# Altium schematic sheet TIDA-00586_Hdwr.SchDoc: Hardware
size 431 x 279 mm; Date: Not shown in title block; ApprovedBy: Not shown in title block; CheckedBy: Not shown in title block; Author: Not shown in title block; CompanyName: Not shown in title block; DrawnBy: Jared Casey; Engineer: Not shown in title block; Organization: Not shown in title block; Address1: Not shown in title block; Address2: Not shown in title block; Address3: Not shown in title block; Address4: Not shown in title block; DocumentNumber: 1; Revision: Use project parameter SCH_Rev; SheetNumber: 7; SheetTotal: 7; PageSetup: Record=PageOptions¦CenterHorizontal=True¦CenterVertical=True¦PrintScale=1.00¦XCorrection=1.00¦YCorrection=1.00¦PrintKind=0¦BorderSize=5000000¦LeftOffset=0¦BottomOffset=0¦Orientation=2¦PaperLength=1000¦PaperWidth=1000¦Scale=100¦PaperSource=15¦PrintQuality=600¦MediaType=1¦DitherType=10¦PaperKind=Letter¦PrintScaleMode=1
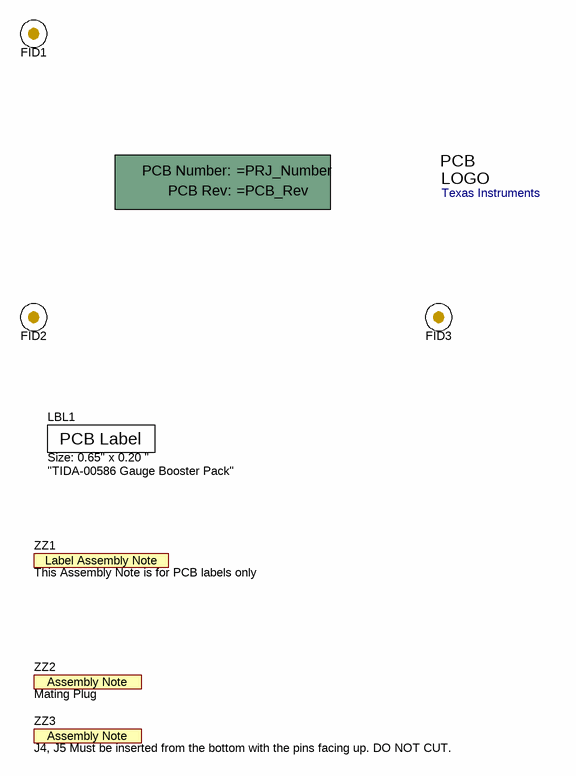
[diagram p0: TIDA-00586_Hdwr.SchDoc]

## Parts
!PCB1  Printed Circuit Board  (value not drawn)  (mechanical)
FID1  Fiducial  [Fiducial10-30]  (value not drawn)
FID2  Fiducial  [Fiducial10-30]  (value not drawn)
FID3  Fiducial  [Fiducial10-30]  (value not drawn)
LBL1  Size: 0.65" x 0.20 "  value "TIDA-00586 Gauge Booster Pack"  [Label_650x200]
Logo1  Texas Instruments  [TI_Stacked_Overlay_Medium]  (no BOM)
ZZ1  This Assembly Note is for PCB labels only  [AssemblyNoteLabel]  (no BOM)
ZZ2  Mating Plug  [AssemblyNote]
ZZ3  J4, J5 Must be inserted from the bottom with the pins facing up. DO NOT CUT.  [AssemblyNote]  (no BOM)

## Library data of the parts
!PCB1 = PCB: Manufacturer: Any; SymbolCreator: a0412235
FID1-FID3 = Fiducial: Fiducial mark.  There is nothing to buy or mount.; SymbolCreator: codlsc
LBL1 = THT-14-423-10: Thermal Transfer Printable Labels, 0.650" W x 0.200" H - 10,000 per roll; Manufacturer: Brady; SymbolCreator: a0412235; CompType: Label
Logo1 = TI_Logo: Texas Instrument Corporate Signature; SymbolCreator: a0412235
ZZ1 = AssemblyNoteLabel: SymbolCreator: a0412235
ZZ2 = AssemblyNote: This is the mating Plug for Connector J1; Manufacturer: On-Shore Technology; PartNumber: OSTTJ0311530; SymbolCreator: codlsc
ZZ3 = AssemblyNote: Manufacturer: On-Shore Technology; PartNumber: OSTTJ0311530; SymbolCreator: codlsc; Value: Plug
